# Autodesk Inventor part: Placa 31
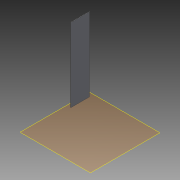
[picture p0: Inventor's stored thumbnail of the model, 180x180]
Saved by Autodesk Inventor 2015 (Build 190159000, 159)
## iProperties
Created: 2015-04
Part Number: Placa 31
Material: Generic
Document SubType Name: Modeling
Designer: suporte
Density: 1 g/cm^3
Appearance: Default
Author: suporte
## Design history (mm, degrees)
workplane "Work Plane1"
sketch "Sketch1"
  geometry: L1 (-900, 875)-(-800, 875) reference; L2 (-900, 875)-(-887.5, 875); L3 (-887.5, 875)-(-887.5, 440); L4 (-887.5, 440)-(-900, 440); L5 (-900, 440)-(-900, 875); L6 (-900, 425)-(-887.5, 425) reference; 1 further point
  constraints: 8 end point, 2 parallel, 1 horizontal, 1 perpendicular
  dimensions: "d0" = 12.5 distance of L3.end L4.end; "d4" = 15 distance between parallel lines of L6 L4
extrude "Extrusion1" new body sketch "Sketch1" distance "d2" = 2100; taper "d3" = 0 deg
body "Solid1"
node "Reference1"
node "Reference2"
